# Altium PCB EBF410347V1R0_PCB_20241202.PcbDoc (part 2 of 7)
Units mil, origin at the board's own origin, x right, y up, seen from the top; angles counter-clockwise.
Board outline 5098.43 x 3464.57 mil, 6 copper layers (TOP, GND02, ART03, ART04, PWR05, BOTTOM), stack 47.2 mil thick; 566 components, 452 nets, 1905 pads, 1432 vias.
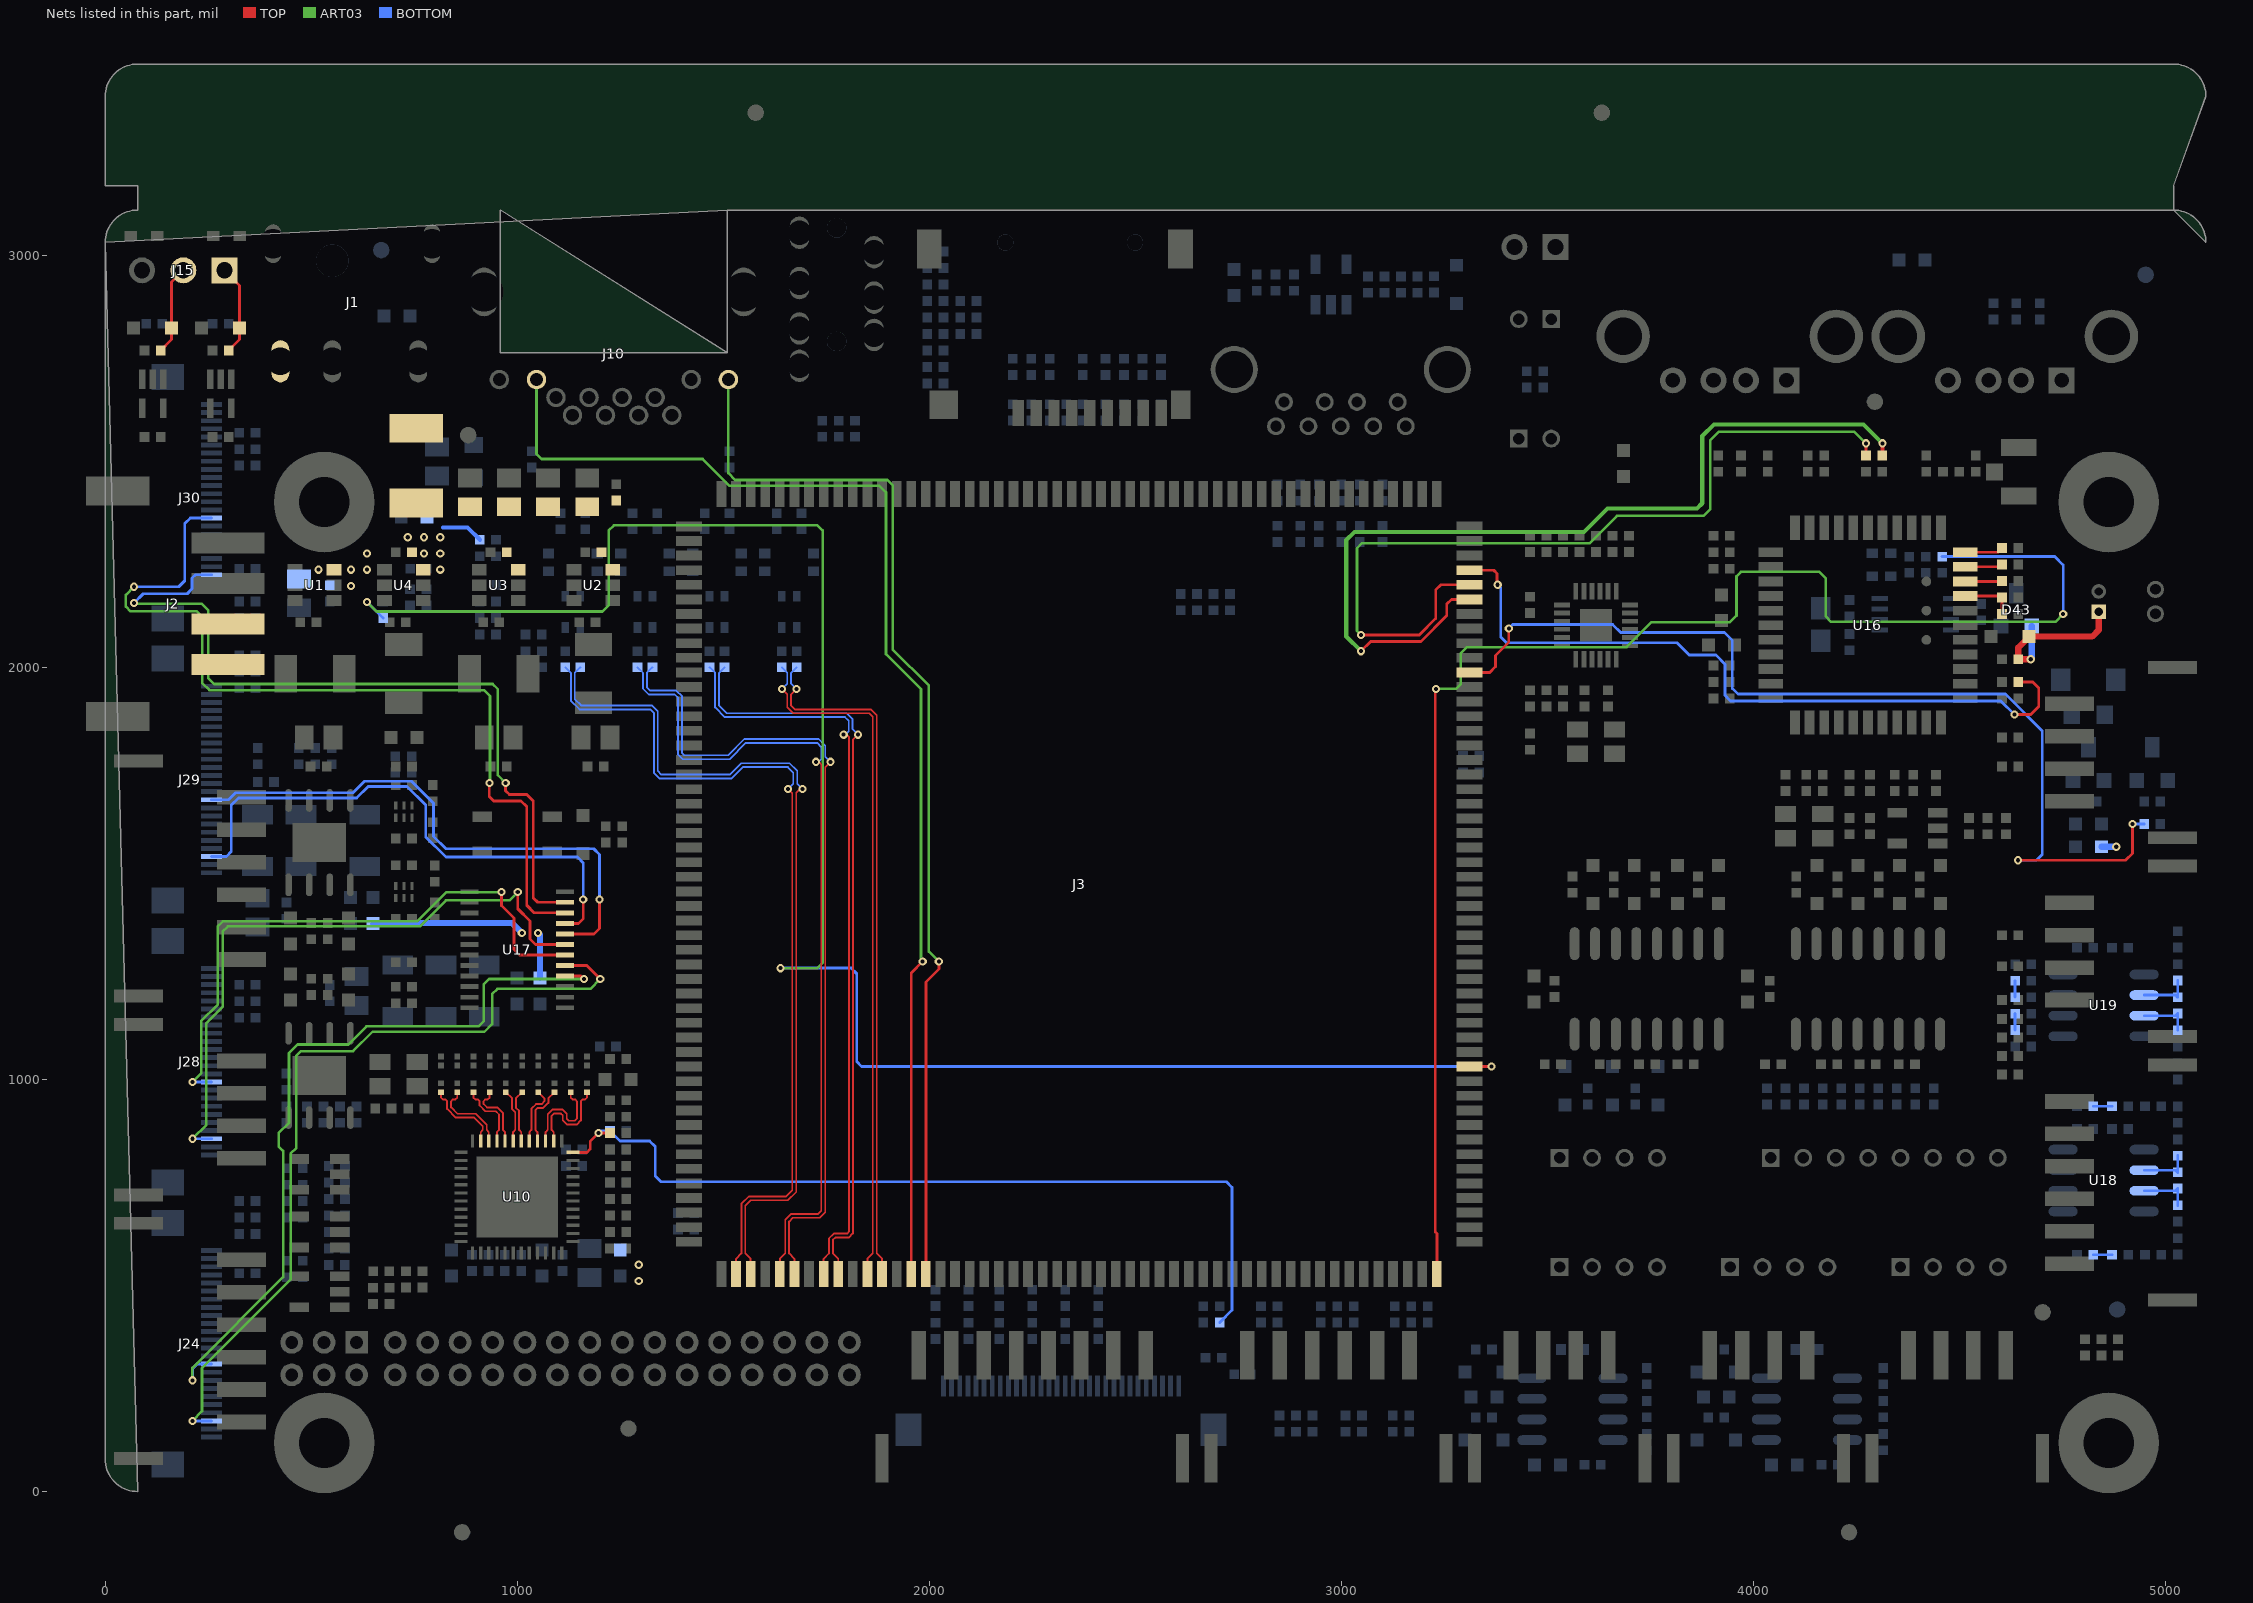
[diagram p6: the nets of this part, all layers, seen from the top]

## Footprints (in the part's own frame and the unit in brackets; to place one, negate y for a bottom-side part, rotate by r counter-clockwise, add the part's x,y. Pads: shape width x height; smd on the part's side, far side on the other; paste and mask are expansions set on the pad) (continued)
HH200-0R90-48R1X48R1-B [mm] "HH200-0R90-48R1X48R1-B"
  rect 0.6x1.6 smd: 1(-22.05,-24.05) 2(-21.15,-24.05) 3(-20.25,-24.05) 4(-19.35,-24.05) 5(-18.45,-24.05) 6(-17.55,-24.05) 7(-16.65,-24.05) 8(-15.75,-24.05) 9(-14.85,-24.05) 10(-13.95,-24.05) 11(-13.05,-24.05) 12(-12.15,-24.05) 13(-11.25,-24.05) 14(-10.35,-24.05) 15(-9.45,-24.05) 16(-8.55,-24.05) 17(-7.65,-24.05) 18(-6.75,-24.05) 19(-5.85,-24.05) 20(-4.95,-24.05) 21(-4.05,-24.05) 22(-3.15,-24.05) 23(-2.25,-24.05) 24(-1.35,-24.05) 25(-0.45,-24.05) 26(0.45,-24.05) 27(1.35,-24.05) 28(2.25,-24.05) 29(3.15,-24.05) 30(4.05,-24.05) 31(4.95,-24.05) 32(5.85,-24.05) 33(6.75,-24.05) 34(7.65,-24.05) 35(8.55,-24.05) 36(9.45,-24.05) 37(10.35,-24.05) 38(11.25,-24.05) 39(12.15,-24.05) 40(13.05,-24.05) 41(13.95,-24.05) 42(14.85,-24.05) 43(15.75,-24.05) 44(16.65,-24.05) 45(17.55,-24.05) 46(18.45,-24.05) 47(19.35,-24.05) 48(20.25,-24.05) 49(21.15,-24.05) 50(22.05,-24.05) 101(22.05,24.05) 102(21.15,24.05) 103(20.25,24.05) 104(19.35,24.05) 105(18.45,24.05) 106(17.55,24.05) 107(16.65,24.05) 108(15.75,24.05) 109(14.85,24.05) 110(13.95,24.05) 111(13.05,24.05) 112(12.15,24.05) 113(11.25,24.05) 114(10.35,24.05) 115(9.45,24.05) 116(8.55,24.05) 117(7.65,24.05) 118(6.75,24.05) 119(5.85,24.05) 120(4.95,24.05) 121(4.05,24.05) 122(3.15,24.05) 123(2.25,24.05) 124(1.35,24.05) 125(0.45,24.05) 126(-0.45,24.05) 127(-1.35,24.05) 128(-2.25,24.05) 129(-3.15,24.05) 130(-4.05,24.05) 131(-4.95,24.05) 132(-5.85,24.05) 133(-6.75,24.05) 134(-7.65,24.05) 135(-8.55,24.05) 136(-9.45,24.05) 137(-10.35,24.05) 138(-11.25,24.05) 139(-12.15,24.05) 140(-13.05,24.05) 141(-13.95,24.05) 142(-14.85,24.05) 143(-15.75,24.05) 144(-16.65,24.05) 145(-17.55,24.05) 146(-18.45,24.05) 147(-19.35,24.05) 148(-20.25,24.05) 149(-21.15,24.05) 150(-22.05,24.05)
  rect 1.6x0.6 smd: 51(24.05,-22.05) 52(24.05,-21.15) 53(24.05,-20.25) 54(24.05,-19.35) 55(24.05,-18.45) 56(24.05,-17.55) 57(24.05,-16.65) 58(24.05,-15.75) 59(24.05,-14.85) 60(24.05,-13.95) 61(24.05,-13.05) 62(24.05,-12.15) 63(24.05,-11.25) 64(24.05,-10.35) 65(24.05,-9.45) 66(24.05,-8.55) 67(24.05,-7.65) 68(24.05,-6.75) 69(24.05,-5.85) 70(24.05,-4.95) 71(24.05,-4.05) 72(24.05,-3.15) 73(24.05,-2.25) 74(24.05,-1.35) 75(24.05,-0.45) 76(24.05,0.45) 77(24.05,1.35) 78(24.05,2.25) 79(24.05,3.15) 80(24.05,4.05) 81(24.05,4.95) 82(24.05,5.85) 83(24.05,6.75) 84(24.05,7.65) 85(24.05,8.55) 86(24.05,9.45) 87(24.05,10.35) 88(24.05,11.25) 89(24.05,12.15) 90(24.05,13.05) 91(24.05,13.95) 92(24.05,14.85) 93(24.05,15.75) 94(24.05,16.65) 95(24.05,17.55) 96(24.05,18.45) 97(24.05,19.35) 98(24.05,20.25) 99(24.05,21.15) 100(24.05,22.05) 151(-24.05,22.05) 152(-24.05,21.15) 153(-24.05,20.25) 154(-24.05,19.35) 155(-24.05,18.45) 156(-24.05,17.55) 157(-24.05,16.65) 158(-24.05,15.75) 159(-24.05,14.85) 160(-24.05,13.95) 161(-24.05,13.05) 162(-24.05,12.15) 163(-24.05,11.25) 164(-24.05,10.35) 165(-24.05,9.45) 166(-24.05,8.55) 167(-24.05,7.65) 168(-24.05,6.75) 169(-24.05,5.85) 170(-24.05,4.95) 171(-24.05,4.05) 172(-24.05,3.15) 173(-24.05,2.25) 174(-24.05,1.35) 175(-24.05,0.45) 176(-24.05,-0.45) 177(-24.05,-1.35) 178(-24.05,-2.25) 179(-24.05,-3.15) 180(-24.05,-4.05) 181(-24.05,-4.95) 182(-24.05,-5.85) 183(-24.05,-6.75) 184(-24.05,-7.65) 185(-24.05,-8.55) 186(-24.05,-9.45) 187(-24.05,-10.35) 188(-24.05,-11.25) 189(-24.05,-12.15) 190(-24.05,-13.05) 191(-24.05,-13.95) 192(-24.05,-14.85) 193(-24.05,-15.75) 194(-24.05,-16.65) 195(-24.05,-17.55) 196(-24.05,-18.45) 197(-24.05,-19.35) 198(-24.05,-20.25) 199(-24.05,-21.15) 200(-24.05,-22.05)
  silkscreen extent -26.5,-26.5 26.5,26.5, body extent -24.9,-24.9 24.9,24.9, height 3.81
L4_2012_T [mm] "L4_2012_T"
  rect 0.675x0.475 smd: 1(-0.963,0.463) 2(0.963,0.463) 3(0.963,-0.463) 4(-0.963,-0.463)
  silkscreen extent -1.5,-0.9 1.5,0.9, body extent -1.5,-0.9 1.5,0.9, height 3.81
L4_3216_T [mm] "L4_3216_T"
  rect 0.7x0.6 smd: 1(-1.5,0.55) 2(1.5,0.55) 3(1.5,-0.55) 4(-1.5,-0.55)
  silkscreen extent -2.1,-1.1 2.1,1.1, body extent -2.1,-1.1 2.1,1.1, height 3.81
L0603#1 [mil] "L0603"
  rect 31.5x31.5 smd: 1(31.5,0) 2(-31.5,0)
  silkscreen extent -55,-24 54,24, body extent -47,-16 47,16, height 150
L0603#2 [mil] "L0603"
  rect 31.5x31.5 smd: 1(-31.5,0) 2(31.5,0)
  silkscreen extent -54,-24 55,24, body extent -47,-16 47,16, height 150
L4520 [mm] "L4520"
  rect 1.4x2.3 smd: 1(-1.803,-0.002) 2(1.798,-0.002)
  silkscreen extent -2.3,-2.2 2.3,2.2, body extent -2.3,-2.2 2.3,2.2, height 3.81
LED_HS_0602_UR [mil] "LED_HS_0602_UR"
  rect 30.31x23.62 smd: 1(-32.09,-15.75) 2(32.09,-15.75)
  silkscreen extent -54,-28 32,28
MSOP-8 [mm] "MSOP-8"
  rect 0.3x1 smd: 1(-0.975,-2.2) 2(-0.325,-2.2) 3(0.325,-2.2) 4(0.975,-2.2) 5(0.975,2.2) 6(0.325,2.2) 7(-0.325,2.2) 8(-0.975,2.2)
  silkscreen extent -1.5,-3.3 1.5,1.5, body extent -1.5,-2.8 1.5,2.8, height 3.81
PH2R0-A-1X4 [mm] "PH2R0-A-1X4"
  rect 0.9x3 smd: 1(-3,-3.2) 2(-1,-3.2) 3(1,-3.2) 4(3,-3.2)
  rect 0.8x3 smd: 5(5.25,3.15) 6(-5.25,3.15)
  silkscreen extent -6,-4.4 6,4.7, body extent -6.1,-4.8 6.1,4.8, height 3.81
PH2R0-A-1X6 [mm] "PH2R0-A-1X6"
  rect 0.9x3 smd: 1(-4.95,-3.2) 2(-2.95,-3.2) 3(-0.95,-3.2) 4(1.05,-3.2) 5(3.05,-3.2) 6(5.05,-3.2)
  rect 0.8x3 smd: 7(7.3,3.15) 8(-7.2,3.15)
  silkscreen extent -7.95,-4.45 8.05,4.7, body extent -8.05,-4.8 8.05,4.8, height 3.81
PH2R0-A-1X8 [mm] "PH2R0-A-1X8"
  rect 0.9x3 smd: 1(-7,-3.2) 2(-5,-3.2) 3(-3,-3.2) 4(-1,-3.2) 5(1,-3.2) 6(3,-3.2) 7(5,-3.2) 8(7,-3.2)
  rect 0.8x3 smd: 9(9.25,3.15) 10(-9.25,3.15)
  silkscreen extent -10,-5.76 10,4.7, body extent -10,-4.8 10,4.8, height 3.81
PH-1X2-2P0_L [mm] "PH-1X2-2P0_L"
  rect 1.1x1.1 hole 0.7: 1(-1,-0.6)
  round 1.1 hole 0.7: 2(1,-0.6)
  silkscreen extent -3,-2.6 3,2.6, body extent -3.1,-2.7 3.1,2.7, height 3.81
PH-1X4-2P0 [mm] "PH-1X4-2P0"
  rect 1.1x1.1 hole 0.7: 1(-3,-0.6)
  round 1.1 hole 0.7: 2(-1,-0.6) 3(1,-0.6) 4(3,-0.6)
  silkscreen extent -5,-2.6 5,2.6, body extent -5.1,-2.7 5.1,2.7, height 3.81
PH-1X8-2P0 [mm] "PH-1X8-2P0"
  rect 1.1x1.1 hole 0.7: 1(-7,-0.6)
  round 1.1 hole 0.7: 2(-5,-0.6) 3(-3,-0.6) 4(-1,-0.6) 5(1,-0.6) 6(3,-0.6) 7(5,-0.6) 8(7,-0.6)
  silkscreen extent -9,-2.6 9,2.6, body extent -9.1,-2.7 9.1,2.7, height 3.81
PTH_M3 [mil] "PTH_M3"
  round 244.09 hole 122.05: 1(0,0)
  body extent -126,-126 126,126, height 150
QFN24 [mm] "QFN24"
  rect 1x0.3 smd: 1(-2.1,1.25) 2(-2.1,0.75) 3(-2.1,0.25) 4(-2.1,-0.25) 5(-2.1,-0.75) 6(-2.1,-1.25) 13(2.1,-1.25) 14(2.1,-0.75) 15(2.1,-0.25) 16(2.1,0.25) 17(2.1,0.75) 18(2.1,1.25)
  rect 0.3x1 smd: 7(-1.25,-2.1) 8(-0.75,-2.1) 9(-0.25,-2.1) 10(0.25,-2.1) 11(0.75,-2.1) 12(1.25,-2.1) 19(1.25,2.1) 20(0.75,2.1) 21(0.25,2.1) 22(-0.25,2.1) 23(-0.75,2.1) 24(-1.25,2.1)
  rect 2x2 smd: 25(0,0)
  silkscreen extent -3.35,-2.1 2.1,2.1, body extent -2.7,-2.7 2.7,2.7, height 3.81
QFN45-0R50-7R10X7R10EP5R40X5R40 [mm] "QFN45-0R50-7R10X7R10EP5R40X5R40"
  rect 0.2x0.8 smd: 1(-2.75,-3.45) 2(-2.25,-3.45) 3(-1.75,-3.45) 4(-1.25,-3.45) 5(-0.75,-3.45) 6(-0.25,-3.45) 7(0.25,-3.45) 8(0.75,-3.45) 9(1.25,-3.45) 10(1.75,-3.45) 11(2.25,-3.45) 12(2.75,-3.45) 25(2.75,3.45) 26(2.25,3.45) 27(1.75,3.45) 28(1.25,3.45) 29(0.75,3.45) 30(0.25,3.45) 31(-0.25,3.45) 32(-0.75,3.45) 33(-1.25,3.45) 34(-1.75,3.45) 35(-2.25,3.45) 36(-2.75,3.45)
  rect 0.8x0.2 smd: 13(3.45,-2.75) 14(3.45,-2.25) 15(3.45,-1.75) 16(3.45,-1.25) 17(3.45,-0.75) 18(3.45,-0.25) 19(3.45,0.25) 20(3.45,0.75) 21(3.45,1.25) 22(3.45,1.75) 23(3.45,2.25) 24(3.45,2.75) 37(-3.45,2.75) 38(-3.45,2.25) 39(-3.45,1.75) 40(-3.45,1.25) 41(-3.45,0.75) 42(-3.45,0.25) 43(-3.45,-0.25) 44(-3.45,-0.75) 45(-3.45,-1.25) 46(-3.45,-1.75) 47(-3.45,-2.25) 48(-3.45,-2.75)
  rect 5x5 smd: 49(0,0)
  silkscreen extent -3.5,-4.55 3.5,3.5, body extent -3.9,-3.9 3.9,3.9, height 3.81
R0201 [mm] "R0201"
  rect 0.35x0.35 smd: 1(-0.275,0) 2(0.275,0)
  silkscreen extent -0.51,-0.25 0.51,0.25, body extent -0.48,-0.18 0.48,0.17, height 3.81
R0402#1 [mil] "R0402"
  rect 23.6x23.6 smd: 1(19.68,0) 2(-19.68,0)
  silkscreen extent -37,-17 37,17, body extent -37,-17 37,17, height 150
R0402#2 [mil] "R0402"
  rect 23.6x23.6 smd: 1(-19.68,0) 2(19.68,0)
  silkscreen extent -37,-17 37,17, body extent -37,-17 37,17, height 150
R0603#1 [mil] "R0603"
  rect 31.5x31.5 smd: 1(-31.5,0) 2(31.5,0)
  silkscreen extent -55,-24 55,24, body extent -47,-16 47,16, height 150
R0603#2 [mil] "R0603"
  rect 31.5x31.5 smd: 1(31.5,0) 2(-31.5,0)
  silkscreen extent -55,-24 54,24, body extent -47,-16 47,16, height 150
R0805 [mil] "R0805"
  rect 40x45 smd: 1(-40,0) 2(40,0)
  silkscreen extent -70,-35 70,35, body extent -60,-25 60,25, height 150
RJ8-15R2X16R2-TM-LED [mm] "RJ8-15R2X16R2-TM-LED"
  round 1.2 hole 0.8: 1(-3.32,-6.35) 2(-2.3,-7.45) 3(-1.28,-6.35) 4(-0.26,-7.45) 5(0.76,-6.35) 6(1.78,-7.45) 7(2.8,-6.35) 8(3.82,-7.45) 9(-6.81,-5.25) 10(-4.52,-5.25) 11(5.02,-5.25) 12(7.31,-5.25)
  oval 1.6x3 hole 2.4 slot 1 at 0 deg: 13(-7.75,0.15) 14(8.25,0.15)
  silkscreen extent -7.75,-7.15 8.25,8.1, body extent -8.75,-8.15 8.75,8.15, height 3.81
SOD323_T#1 [mil] "SOD323_T"
  rect 31.5x31.5 smd: 1(-46.26,0) 2(46.26,0)
  silkscreen extent -35,-28 35,28, body extent -63,-28 63,28, height 150
SOD323_T#2 [mil] "SOD323_T"
  rect 31.5x31.5 smd: 1(46.26,0) 2(-46.26,0)
  silkscreen extent -35,-28 35,28, body extent -63,-28 63,28, height 150
SOD523#1 [mm] "SOD523"
  rect 0.6x0.7 smd: 1(-0.71,0) 2(0.71,0)
  silkscreen extent -1.3,-0.5 0.6,0.5, body extent -1.1,-0.4 1.1,0.4, height 3.81
SOD523#2 [mm] "SOD523"
  rect 0.6x0.7 smd: 1(0.71,0) 2(-0.71,0)
  silkscreen extent -0.6,-0.5 1.3,0.5, body extent -1.1,-0.4 1.1,0.4, height 3.81
SOD-123 [mm] "SOD-123"
  rect 1.2x1.4 smd: 1(1.7,0) 2(-1.7,0)
  silkscreen extent -1.8,-0.9 2.8,0.9, body extent -2.4,-1 2.4,1, height 3.81
SOIC16 [mil] "SOIC16"
  oval 80x24 smd: 1(-109.8,174.8) 2(-109.8,125.2) 3(-109.8,74.8) 4(-109.8,25.2) 5(-109.8,-25.2) 6(-109.8,-74.8) 7(-109.8,-125.2) 8(-109.8,-174.8) 9(109.8,-174.8) 10(109.8,-125.2) 11(109.8,-74.8) 12(109.8,-25.2) 13(109.8,25.2) 14(109.8,74.8) 15(109.8,125.2) 16(109.8,174.8)
  silkscreen extent -179,-197 59,197, body extent -157,-205 157,205, height 150
SOP8 [mm] "SOP8"
  oval 0.6x1.8 smd: 1(-1.905,-2.5) 2(-0.635,-2.5) 3(0.635,-2.5) 4(1.905,-2.5) 5(1.905,2.5) 6(0.635,2.5) 7(-0.635,2.5) 8(-1.905,2.5)
  silkscreen extent -2.5,-4.15 2.5,1.4, body extent -2.5,-3.5 2.5,3.5, height 3.81
SOP-8-EP-2R5X3R4 [mm] "SOP-8-EP-2R5X3R4"
  oval 0.4x1.4 smd: 1(-1.905,-2.6) 2(-0.635,-2.6) 3(0.635,-2.6) 4(1.905,-2.6) 5(1.905,2.6) 6(0.635,2.6) 7(-0.635,2.6) 8(-1.905,2.6)
  rect 3.3x2.4 smd: 9(0,0)
  silkscreen extent -2.5,-3.95 2.5,2, body extent -2.5,-3 2.5,3, height 3.81
SOT23 [mil] "SOT23"
  rect 36x36 smd: 1(37.5,43.5) 2(-37.5,43.5)
  rect 36x50 smd: 3(0,-36.5)
  silkscreen extent -55,-36 55,54, body extent -56,-62 56,62, height 150
SOT23-5#1 [mm] "SOT23-5"
  rect 0.599x1.199 smd: 1(0.95,1.25) 2(0,1.25) 3(-0.95,1.25) 4(-0.95,-1.25) 5(0.95,-1.25)
  silkscreen extent -1.5,-0.9 1.5,2.55, body extent -1.6,-1.9 1.6,1.9, height 3.81
SOT23-5#2 [mm] "SOT23-5"
  rect 0.599x1.199 smd: 1(-0.95,-1.25) 2(0,-1.25) 3(0.95,-1.25) 4(0.95,1.25) 5(-0.95,1.25)
  silkscreen extent -1.5,-2.55 1.5,0.9, body extent -1.6,-1.9 1.6,1.9, height 3.81
SOT23_6 [mm] "SOT23_6"
  rect 0.7x0.9 smd: 1(-0.95,-1.2) 2(0,-1.2) 3(0.95,-1.2) 4(0.95,1.2) 5(0,1.2) 6(-0.95,1.2)
  silkscreen extent -2.19,-1.25 1.4,0.6, body extent -1.4,-1.2 1.4,1.2, height 3.81
SOT-353 [mil] "SOT-353"
  rect 16x47 smd: 1(-25.91,-35.43) 2(-0.31,-35.43) 3(25.28,-35.43) 4(25.28,35.43) 5(-25.91,35.43)
  silkscreen extent -55,-80 45,70, body extent -40,-65 40,65, height 150
SW4-4R20X3R25-SM [mm] "SW4-4R20X3R25-SM"
  rect 1.2x0.65 smd: 1(-2.15,1.075) 2(2.15,1.075) 3(2.15,-1.075) 4(-2.15,-1.075)
  silkscreen extent -2.1,-1.6 2.1,1.6, body extent -2.8,-1.7 2.8,1.7, height 3.81
TFCARD [mm] "TFCARD"
  rect 0.7x1.6 smd: 1(2.25,5.253) 2(1.15,5.253) 3(0.05,5.253) 4(-1.05,5.253) 5(-2.15,5.253) 6(-3.25,5.253) 7(-4.35,5.253) 8(-5.45,5.253) 9(-6.55,5.253)
  rect 1.2x1.778 smd: 10(-7.75,4.753)
  rect 1.524x2.413 smd: 11(-7.75,-4.847) 12(7.75,-4.847)
  rect 1.778x1.778 smd: 13(6.85,4.753)
  round 1 hole 1 unplated: ""(-4.95,-5.247) ""(3.05,-5.247)
  silkscreen extent -7.34,-9.27 7.13,4.55, body extent -8.51,-6.05 8.51,6.05, height 3.81
TSSOP24-0R65-7R80X4R40 [mm] "TSSOP24-0R65-7R80X4R40"
  rect 1.1x0.3 smd: 1(-2.95,3.575) 2(-2.95,2.925) 3(-2.95,2.275) 4(-2.95,1.625) 5(-2.95,0.975) 6(-2.95,0.325) 7(-2.95,-0.325) 8(-2.95,-0.975) 9(-2.95,-1.625) 10(-2.95,-2.275) 11(-2.95,-2.925) 12(-2.95,-3.575) 13(2.95,-3.575) 14(2.95,-2.925) 15(2.95,-2.275) 16(2.95,-1.625) 17(2.95,-0.975) 18(2.95,-0.325) 19(2.95,0.325) 20(2.95,0.975) 21(2.95,1.625) 22(2.95,2.275) 23(2.95,2.925) 24(2.95,3.575)
  silkscreen extent -4.1,-3.9 2.2,3.9, body extent -3.6,-4.1 3.6,4.1, height 3.81
UFL-3 [mm] "UFL-3"
  rect 1.05x1.05 smd: 1(0,-1.038)
  rect 1.05x2.2 smd: 2(-1.5,0.462) 3(1.5,0.462)
  body extent -2.02,-1.56 2.02,1.56, height 3.81
USB9-A-16R5X14R45-TM [mm] "USB9-A-16R5X14R45-TM"
  round 1.1 hole 0.7: 1(-3.5,5.6) 2(-1,5.6) 3(1,5.6) 4(3.5,5.6) 5(4,7.1) 6(2,7.1) 7(0,7.1) 8(-2,7.1) 9(-4,7.1)
  round 2.9 hole 2.3: 10(-6.57,3.6) 11(6.57,3.6)
  silkscreen extent -7.23,-8.23 7.22,8.27, body extent -8.1,-8.3 8.1,8.3, height 3.81
USB-A-SM [mm] "USB-A-SM"
  rect 1.6x1.6 / inner round 1.6 / far side rect 1.6x1.6 hole 0.9: 1(-3.487,5.537)
  round 1.6 hole 0.9: 2(-0.987,5.537) 3(1.013,5.537) 4(3.513,5.537)
  round 3.3 hole 2.3: 5(-6.557,2.823) 6(6.583,2.823)
  silkscreen extent -6.59,-6.96 6.61,7.04, body extent -8.22,-7.16 8.22,7.16, height 3.81
X2-DFN1410-6 [mm] "X2-DFN1410-6"
  rect 0.2x0.5 smd: 1(-0.5,-0.375) 2(0,-0.375) 3(0.5,-0.375) 4(0.5,0.375) 5(0,0.375) 6(-0.5,0.375)
  silkscreen extent -0.8,-1.06 0.8,0.5, body extent -0.9,-0.7 0.9,0.7, height 3.81
ZH1P5MM_TH_2P [mm] "ZH1P5MM_TH_2P"
  round 1.05 hole 0.65: 1(-0.75,0.65) 2(0.75,0.65)
  silkscreen extent -2.25,-1.85 2.25,1.85, body extent -2.2,-1.85 2.2,1.85, height 3.81

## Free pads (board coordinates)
  round 40 smd far side: 1(670,3013) 1(4883,442) 1(4952,2953)
  round 40 / inner round 60 / far side round 40 all layers, no hole: 1(866.14,-98.74) 1(1578.74,3346.46) 1(3632.28,3346.46) 1(4232.28,-98.74)
  round 40 smd: 1(881,2564) 1(1270,153) 1(4295,2645) 1(4702,435)

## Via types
v1: diameter 20, hole 10, TOP to BOTTOM, 1432 vias

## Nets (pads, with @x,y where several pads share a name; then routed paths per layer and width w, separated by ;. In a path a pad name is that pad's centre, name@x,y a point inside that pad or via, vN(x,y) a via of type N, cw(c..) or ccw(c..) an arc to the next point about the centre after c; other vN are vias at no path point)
12V: C5.1 C6.1 C7.1 C8.1 C9.1 C18.1 C19.1 C20.1 C21.1 C26.1 C27.1 F1.2 R8.2 R19.1 R30.1 R79.1 R133.1 U1.3 U2.3 U3.3 U4.3 | length 620.9
  BOTTOM w10: 820,2340 879.32,2340 R8.2@909.32,2310 ; v1(1011.22,1355.63) v1@1011.22,1355.78
  BOTTOM w15: R30.1@650,1378.5 651.5,1380 987,1380 v1@1011.22,1355.78 ; v1(1050.59,1355.63) 1055,1351.22 R19.1@1055,1246.5 ; R133.1@4844.61,1565 v1(4880.74,1565)
  other v1: 1295,511.26 1295,550.63 596.3,2198.03 517.56,2237.4 596.3,2237.4 635.67,2237.4 813.15,2237.4 635.67,2276.77 773.78,2276.77 813.15,2276.77 734.41,2316.14 773.78,2316.14 813.15,2316.14
12V_IN: F1.1 J1.4 J2.3 J2.4
BAT_RTC: C116.1 D43.1 D44.2 J23.1 | length 397.5
  TOP w15: v1(4673.11,2020) C116.1@4642.79,2020 4642.79,2048.42 D44.2@4669.37,2075 4822.11,2075 4838.11,2091 J23.1@4838.11,2135.35
  BOTTOM w15: v1(4673.11,2020) 4675.61,2022.5 D43.1@4675.61,2100.37
BT_HOST_WAKE: J3.46 R158.1 | length 2059.1
  TOP w6.8: v1(3048,2079) 3189,2079 3229,2119 3229,2188 3241.75,2200.75 J3.46@3310.59,2200.75 ; R158.1@4273.11,2514.68 v1(4273.11,2544)
  ART03 w6.3: v1(3048,2079) 3038,2089 3038,2289.4 3050.6,2302 3603,2302 3669.15,2368.15 3879.15,2368.15 3895,2384 3895,2551.4 3915.6,2572 4245.11,2572 v1(4273.11,2544)
BT_REG_ON: J3.47 R155.2 | length 1765.8
  TOP w6.8: J3.47@3310.59,2236.18 3369.82,2236.18 3378,2228 3378,2202.14 v1(3379.37,2200.77) ; v1(4633.74,1885.63) 4673.11,1885.63 4692.51,1905.03 4692.51,1950.6 4678.11,1965 R155.2@4642.79,1965
  BOTTOM w6.8: v1(3379.37,2200.77) 3387,2193.14 3387,2073.6 3400.6,2060 3814.51,2060 3844.51,2030 3909,2030 3931,2008 3931,1932.6 3944.6,1919 4600.37,1919 v1(4633.74,1885.63)
BT_UART_CTS: R154.2 U16.44 | length 93.4
  TOP w6.8: U16.44@4514.33,2279.73 4593.16,2279.73 R154.2@4603.43,2290
BT_UART_RTS: R129.1 R150.2 U16.41 | length 130.5
  TOP w6.8: U16.41@4514.33,2173.43 4600,2173.43 R150.2@4603.43,2170 R129.1@4603.43,2130
BT_UART_RXD: R153.2 U16.43 | length 91.5
  TOP w6.8: U16.43@4514.33,2244.29 4597.72,2244.29 R153.2@4603.43,2250
BT_UART_TXD: R152.2 U16.42 | length 89.6
  TOP w6.8: U16.42@4514.33,2208.86 4602.29,2208.86 R152.2@4603.43,2210
BT_WAKE: J3.45 R156.1 | length 2176.7
  TOP w6.8: v1(3048,2039.63) 3071.37,2063 3193,2063 3256,2126 3256,2154 3267.32,2165.32 J3.45@3310.59,2165.32
  TOP w10: R156.1@4313.11,2514.68 v1(4313.11,2544)
  ART03 w10: v1(3048,2039.63) 3012,2075.63 3012,2309 3032,2329 3589,2329 3646,2386 3863.4,2386 3876,2398.6 3876,2561.7 3904.3,2590 4267.11,2590 v1(4313.11,2544)
CAM0_NRST: J24.22 U17.5 | length 1993.1
  TOP w6.8: U17.5@1116.14,1276.61 1168.76,1276.61 v1(1201.37,1244)
  ART03 w6.3: v1(211.57,171.57) 235,195 235,300 450,515 450,820 464,834 464,1057.9 474.8,1068.7 601.7,1068.7 649,1116 920.4,1116 939,1134.6 939,1207.4 951.6,1220 1177.37,1220 v1(1201.37,1244)
  BOTTOM w6.8: v1(211.57,171.57) J24.22@257.91,171.57
CAM0_PWDN: J24.15 U17.4 | length 1870.9
  TOP w6.8: U17.4@1116.14,1251.02 1154.98,1251.02 v1(1162,1244)
  ART03 w6.3: v1(211.57,270) 211.57,299.98 432,520.4 432,827 421,838 421,870 446,895 446,1064 467,1085 590,1085 634,1129 906.4,1129 919,1141.6 919,1231.4 931.6,1244 v1(1162,1244)
  BOTTOM w6.8: v1(211.57,270) 212,270.43 212,298 223.37,309.37 J24.15@257.91,309.37
CAM1_NRST: J28.22 U17.7 | length 1551.9
  TOP w6.8: v1(1001.37,1455) 1001.37,1414.63 1031,1385 1031,1341 1044.2,1327.8 U17.7@1116.14,1327.8
  ART03 w6.3: v1(212,856.37) 245.3,889.67 245.3,1136.7 285,1176.4 285,1359.1 297.6,1371.7 763.7,1371.7 827,1435 981.37,1435 v1(1001.37,1455)
  BOTTOM w6.8: v1(212,856.37) J28.22@257.91,856.37
CAM1_PWDN: J28.15 U17.6 | length 1453.7
  TOP w6.8: v1(962,1455) 962,1422 991.82,1392.18 991.82,1315.81 1005.42,1302.2 U17.6@1116.14,1302.2
  ART03 w6.3: v1(212,994.17) 233,1015.16 233,1141.8 272.7,1181.49 272.7,1371.4 285.3,1384 757,1384 828,1455 v1(962,1455)
  BOTTOM w6.8: v1(212,994.17) J28.15@257.91,994.17
CAM2_NRST: J29.22 U17.9 | length 1345
  TOP w6.8: U17.9@1116.14,1378.98 1148.98,1378.98 1160,1390 v1(1160,1437)
  BOTTOM w6.8: J29.22@257.91,1541.17 294.17,1541.17 306,1553 306,1666 323.2,1683.2 610.3,1683.2 638.3,1711.2 732.8,1711.2 778,1666 778,1589 827,1540 1146,1540 1160,1526 v1(1160,1437)
CAM2_PWDN: J29.15 U17.8 | length 1349.5
  TOP w6.8: U17.8@1116.14,1353.39 1186.39,1353.39 1199.37,1366.37 v1(1199.37,1437)
  BOTTOM w6.8: J29.15@257.91,1678.96 298.96,1678.96 316,1696 601,1696 629,1724 743.56,1724 797,1670.56 797,1590 827,1560 1185.77,1560 1199.37,1546.4 v1(1199.37,1437)
CAM3_NRST: J30.22 U17.11 | length 1945.6
  TOP w6.8: v1(971.85,1720) 971.85,1701 980.85,1692 1023,1692 1039,1676 1039,1441 1049.84,1430.16 U17.11@1116.14,1430.16
  ART03 w6.3: v1(70.06,2156.68) 71.74,2155 233.6,2155 250.2,2138.4 250.2,1973.8 264,1960 940.1,1960 952.7,1947.4 952.7,1739.15 v1(971.85,1720)
  BOTTOM w6.8: v1(70.06,2156.68) 92.37,2179 199,2179 211,2191 211,2217 218.96,2224.96 J30.22@257.91,2224.96
CAM3_PWDN: J30.15 U17.10 | length 2148.7
  TOP w6.8: v1(932.48,1720) 932,1719.52 932,1687 943,1676 1009.4,1676 1023,1662.4 1023,1423 1041.43,1404.57 U17.10@1116.14,1404.57
  ART03 w6.3: v1(70.06,2196.05) 50.15,2176.15 50.15,2147.85 61.54,2136.46 222.54,2136.46 235.2,2123.8 235.2,1962.6 252.8,1945 919.88,1945 934,1930.88 934,1721.52 v1(932.48,1720)
  BOTTOM w6.8: v1(70.06,2196.05) 178.4,2196.05 193,2210.65 193,2349.16 206.6,2362.76 J30.15@257.91,2362.76
CAN0_H: R237.1 R238.1 U18.7 | length 124.4
  BOTTOM w6.8: U18.7@4948.43,730 5024.68,730 R237.1@5030,735.32 R238.1@5030,694.68
CAN0_L: R237.2 R251.1 U18.6 | length 124.4
  BOTTOM w6.8: U18.6@4948.43,780 5024.68,780 R237.2@5030,774.68 R251.1@5030,815.32
CAN0_RX_M2: R240.1 R243.2 | length 45.6
  BOTTOM w6.8: R240.1@4824.68,935 R243.2@4870.32,935
CAN0_TX_M2: R239.1 R241.2 | length 45.6
  BOTTOM w6.8: R239.1@4824.68,575 R241.2@4870.32,575
CAN1_H: R247.1 R252.1 U19.7 | length 124.4
  BOTTOM w6.8: U19.7@4948.43,1155 5024.68,1155 R247.1@5030,1160.32 R252.1@5030,1119.68
CAN1_L: R247.2 R258.1 U19.6 | length 124.4
  BOTTOM w6.8: U19.6@4948.43,1205 5024.68,1205 R247.2@5030,1199.68 R258.1@5030,1240.32
CAN1_RX_M1: R246.1 R257.2 | length 40
  BOTTOM w6.8: R246.1@4635.32,1200 R257.2@4635.32,1240
CAN1_TX_M1: R245.1 R248.2 | length 40
  BOTTOM w6.8: R248.2@4635.32,1120 R245.1@4635.32,1160
CLK_32K_IN: J3.200 R135.2 | length 3695.4
  TOP w6.8: v1(3229.85,1948) 3228,1946.15 3228,630 3231.85,626.15 J3.200@3231.85,527.52
  ART03 w6.3: v1(3229.85,1948) 3278,1948 3290,1960 3290,2035 3304.51,2049.51 3692.51,2049.51 3753,2110 3943,2110 3959,2126 3959,2221 3970,2232 4160,2232 4176,2216 4176,2124 4189,2111 4732.85,2111 v1(4751.85,2130)
  BOTTOM w6.8: R135.2@4458.11,2269.05 4664.72,2269.05 4665.07,2269.4 4731.6,2269.4 4751.85,2249.15 v1(4751.85,2130)
DGB_RX: D30.1 J15.2 R70.1 | length 217.4
  TOP w6.8: R70.1@134.68,2769.37 161.26,2795.95 D30.1@161.26,2824.37 161.26,2935.7 J15.2@189.61,2964.05
DGB_TX: D31.1 J15.1 R69.1 | length 220.9
  TOP w6.8: J15.1@289.61,2964.05 326.26,2927.4 D31.1@326.26,2824.37 326.26,2795.95 R69.1@299.68,2769.37
ETH_PHY_LED1: J3.164 J10.10 | length 3013
  TOP w6.8: J3.164@1956.26,527.52 1956.26,1258.77 v1(1983.89,1286.4)
  ART03 w6.3: J10.10@1046.73,2698.82 1046.73,2518.6 1059.33,2506 1450,2506 1515,2441 1879,2441 1895,2425 1895,2032.6 1980,1947.6 1980,1290.29 v1(1983.89,1286.4)
ETH_PHY_LED2: J3.165 J10.12 | length 2612.3
  TOP w6.8: J3.165@1991.69,527.52 1991.69,1236.69 2023.26,1268.26 v1(2023.26,1286.4)
  ART03 w6.3: J10.12@1512.47,2698.82 1512.47,2471.53 1529,2455 1898.4,2455 1911,2442.4 1911,2044 1999,1956 1999,1310.66 v1(2023.26,1286.4)
ETH_PHY_MDIN0: C55.1 J3.153 | length 2148.7
  TOP w4.5: J3.153@1566.5,527.52 1566.5,564.95 1553.53,577.92 1553.53,694.09 1566.44,707 1656.94,707 1677,727.06 1677,1696 1686,1705 v1(1692.29,1705)
  BOTTOM w4.5: C55.1@1153.21,2000.32 1139.75,1986.86 1139.75,1923.25 1155,1908 1327,1908 1341,1894 1341,1749 1350,1740 1515.81,1740 1543.5,1767.69 1660.74,1767.69 1679.5,1748.94 1679.5,1717.79 v1(1692.29,1705)
ETH_PHY_MDIN1: C57.1 J3.156 | length 2032.1
  TOP w4.5: J3.156@1672.8,527.52 1672.8,564.95 1659.83,577.92 1659.83,655.39 1668.94,664.5 1734.5,664.5 1747.5,677.5 1747.5,1758.21 v1(1760.29,1771)
  BOTTOM w4.5: C57.1@1328.21,2000.32 1314.75,1986.86 1314.75,1952.25 1323,1944 1386,1944 1400,1930 1400,1792.44 1405.44,1787 1511.56,1787 1551.06,1826.5 1731.5,1826.5 1747.5,1810.5 1747.5,1783.79 v1(1760.29,1771)
ETH_PHY_MDIN2: C59.1 J3.159 | length 1838.6
  TOP w4.5: J3.159@1779.09,527.52 1779.09,564.95 1766.13,577.92 1766.13,610.69 1771.94,616.5 1804.44,616.5 1814.5,626.56 1814.5,1824.21 v1(1827.29,1837)
  BOTTOM w4.5: C59.1@1503.21,2000.32 1489.75,1986.86 1489.75,1907.25 1508,1889 1799.44,1889 1814,1874.44 1814,1850.29 v1(1827.29,1837)
ETH_PHY_MDIN3: C61.1 J3.162 | length 1688.4
  TOP w4.5: v1(1677.54,1948) 1664.75,1935.21 1664.75,1907.25 1673.5,1898.5 1857.86,1898.5 1872.43,1883.93 1872.43,577.92 1885.39,564.95 J3.162@1885.39,527.52
  BOTTOM w4.5: v1(1677.54,1948) 1664.75,1960.79 1664.75,1986.86 C61.1@1678.21,2000.32
ETH_PHY_MDIP0: C54.1 J3.152 | length 2143
  TOP w4.5: J3.152@1531.06,527.52 1531.06,564.95 1544.03,577.92 1544.03,698.03 1562.5,716.5 1653,716.5 1667.5,731 1667.5,1694.71 v1(1657.21,1705)
  BOTTOM w4.5: C54.1@1116.79,2000.32 1130.25,1986.86 1130.25,1919.31 1151.06,1898.5 1323.06,1898.5 1331.5,1890.06 1331.5,1745.06 1346.06,1730.5 1519.75,1730.5 1547.44,1758.19 1656.81,1758.19 1670,1745 1670,1717.79 v1(1657.21,1705)
ETH_PHY_MDIP1: C56.1 J3.155 | length 2040
  TOP w4.5: J3.155@1637.36,527.52 1637.36,564.95 1650.33,577.92 1650.33,659.33 1665,674 1730.56,674 1738,681.44 1738,1765 1732,1771 v1(1725.21,1771)
  BOTTOM w4.5: C56.1@1291.79,2000.32 1305.25,1986.86 1305.25,1948.31 1319.06,1934.5 1382.06,1934.5 1390.5,1926.06 1390.5,1788.5 1401.5,1777.5 1515.5,1777.5 1555,1817 1727.56,1817 1738,1806.56 1738,1777 1732,1771 v1(1725.21,1771)
ETH_PHY_MDIP2: C58.1 J3.158 | length 1845
  TOP w4.5: J3.158@1743.66,527.52 1743.66,564.95 1756.63,577.92 1756.63,614.63 1768,626 1800.5,626 1805,630.5 1805,1832 1800,1837 v1(1792.21,1837)
  BOTTOM w4.5: C58.1@1466.79,2000.32 1480.25,1986.86 1480.25,1903.31 1504.06,1879.5 1795.5,1879.5 1804.5,1870.5 1804.5,1845.5 1796,1837 v1(1792.21,1837)
ETH_PHY_MDIP3: C60.1 J3.161 | length 1688.4
  TOP w4.5: v1(1642.46,1948) 1655.25,1935.21 1655.25,1903.31 1669.56,1889 1853.93,1889 1862.93,1880 1862.93,577.92 1849.96,564.95 J3.161@1849.96,527.52
  BOTTOM w4.5: C60.1@1641.79,2000.32 1655.25,1986.86 1655.25,1960.79 v1(1642.46,1948)
EXT_PWR_EN: J3.13 R3.2 | length 4527.8
  TOP w6.8: J3.13@3310.59,1031.46 v1(3364.54,1031.46)
  ART03 w6.3: v1(635.67,2158.66) 658.33,2136 1207,2136 1222,2151 1222,2332.4 1234.6,2345 1728.4,2345 1741,2332.4 1741,1283 1728.37,1270.37 v1(1639,1270.37)
  BOTTOM w6.8: v1(635.67,2158.66) 674.01,2120.32 R3.2@675,2120.32 ; v1(1639,1270.37) 1810.4,1270.37 1824,1256.77 1824,1043.81 1835.81,1032 3364,1032 v1(3364.54,1031.46)
FAN_CTRL: J3.40 R137.1 | length 2398.4
  TOP w6.8: J3.40@3310.59,1988.15 3360.15,1988.15 3374,2002 3374,2029 3406.54,2061.54 v1(3406.54,2094.9) ; v1(4641.97,1532.32) 4903.43,1532.32 4920.11,1549 v1(4920.11,1620)
  BOTTOM w6.8: v1(3406.54,2094.9) 3416.18,2104.53 3658.58,2104.53 3678.11,2085 3929.51,2085 3949,2065.51 3949,1949 3962.51,1935.49 4611.62,1935.49 4701,1846.11 4701,1546 4687.32,1532.32 v1(4641.97,1532.32) ; v1(4920.11,1620) R137.1@4948.43,1620
GM8775C_DA0N: R89.2 U10.15 | length 237
  TOP w4.5: U10.15@1068.8,850.83 1068.8,872.51 1073.89,877.6 1073.89,915.89 1085,927 1110,927 1120,917 1120,905 1125,900 1140,900 1144.89,904.89 1144.89,947.35 1140.39,951.85 1134.46,951.85 1129.96,956.35 R89.2@1129.96,969.17
GM8775C_DA0P: R86.2 U10.14 | length 237
  TOP w4.5: U10.14@1088.48,850.83 1088.48,872.51 1083.39,877.6 1083.39,911.96 1088.94,917.5 1106.06,917.5 1110.5,913.06 1110.5,901.06 1121.06,890.5 1143.94,890.5 1154.39,900.96 1154.39,947.35 1158.89,951.85 1164.83,951.85 1169.33,956.35 R86.2@1169.33,969.17
GM8775C_DA1N: R93.2 U10.17 | length 147.6
  TOP w4.5: U10.17@1029.43,850.83 1029.43,872.51 1034.52,877.6 1034.52,929.52 1045.5,940.5 1059.06,940.5 1066,947.44 1066,954.39 R93.2@1051.22,969.17
GM8775C_DA1P: R90.2 U10.16 | length 147.7
  TOP w4.5: U10.16@1049.12,850.83 1049.12,872.51 1044.02,877.6 1044.02,925.59 1049.44,931 1063,931 1075.5,943.5 1075.5,954.08 R90.2@1090.59,969.17
GM8775C_DA2N: R97.2 U10.21 | length 164.4
  TOP w4.5: R97.2@893.74,969.17 893.74,956.35 898.24,951.85 904.17,951.85 908.67,947.35 908.67,937.05 922.72,923 948,923 955.78,915.22 955.78,877.6 950.69,872.51 U10.21@950.69,850.83
GM8775C_DA2P: R94.2 U10.20 | length 164.4
  TOP w4.5: R94.2@933.11,969.17 933.11,956.35 928.61,951.85 922.67,951.85 918.17,947.35 918.17,940.98 926.66,932.5 951.94,932.5 965.28,919.15 965.28,877.6 970.37,872.51 U10.20@970.37,850.83
GM8775C_DA3N: R102.2 U10.23 | length 192
  TOP w4.5: R102.2@815,969.17 815,956.35 819.5,951.85 825.44,951.85 829.94,947.35 829.94,928.63 851.06,907.5 895.5,907.5 916.41,886.59 916.41,877.6 911.32,872.51 U10.23@911.32,850.83
GM8775C_DA3P: R99.2 U10.22 | length 192
  TOP w4.5: R99.2@854.37,969.17 854.37,956.35 849.87,951.85 843.94,951.85 839.44,947.35 839.44,932.56 855,917 899.44,917 925.91,890.52 925.91,877.6 931,872.51 U10.22@931,850.83
GM8775C_DACN: R107.2 U10.19 | length 129.8
  TOP w4.5: R107.2@972.48,969.17 987.41,954.23 987.41,928.06 995.15,920.33 995.15,877.6 990.06,872.51 U10.19@990.06,850.83
GM8775C_DACP: R104.2 U10.18 | length 129.8
  TOP w4.5: U10.18@1009.75,850.83 1009.75,872.51 1004.65,877.6 1004.65,924.26 996.91,932 996.91,954.24 R104.2@1011.85,969.17
GM8775C_RSTN: C95.1 R73.2 R187.2 U10.12 | length 2099.4
  TOP w6.8: U10.12@1135.73,823.27 1169.27,823.27 1177,831 1177,850 v1(1197,870) C95.1@1225.32,870
  BOTTOM w6.8: v1(1197,870) 1202,875 R73.2@1225.32,875 1249.12,851.2 1321.4,851.2 1335,837.6 1335,765.6 1348.6,752 2721.4,752 2735,738.4 2735,440.32 R187.2@2705,410.32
